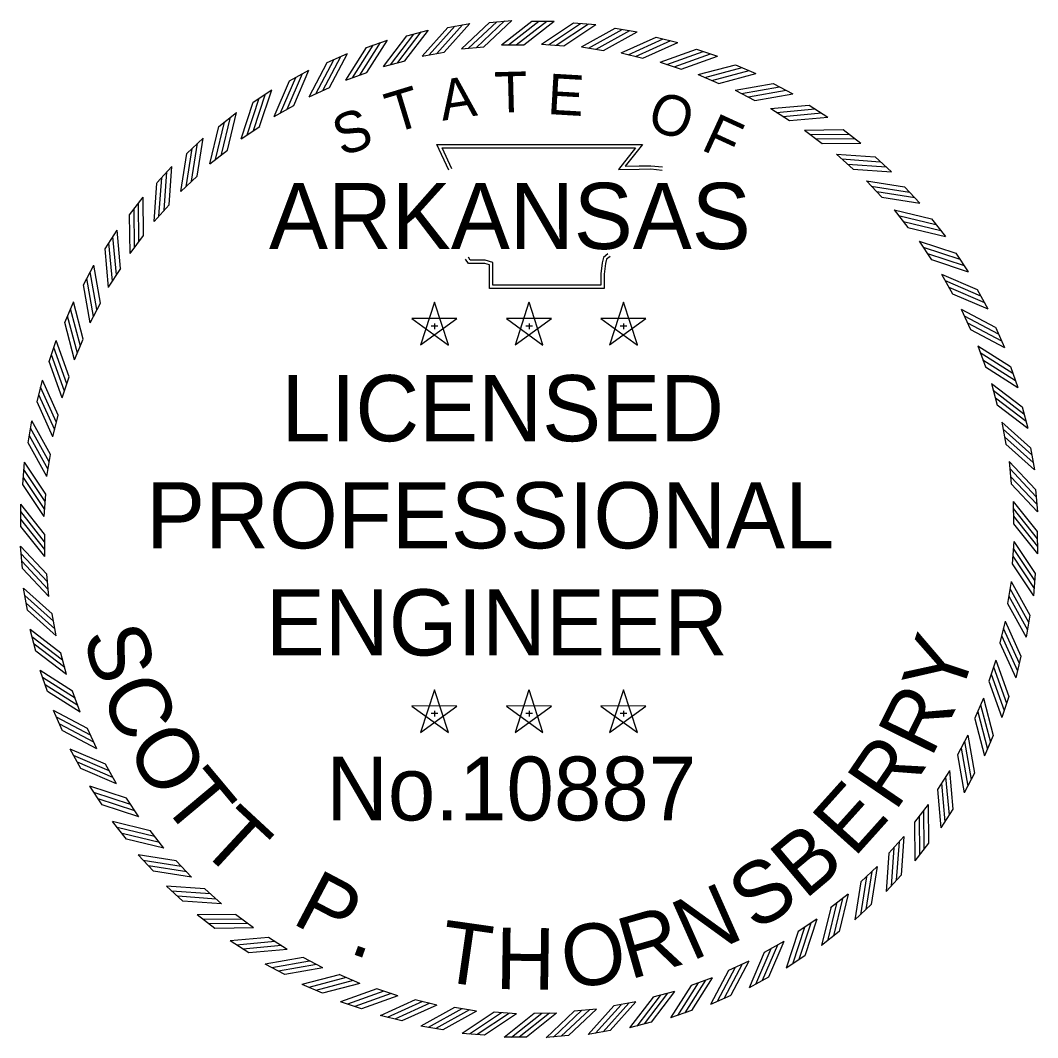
# Model space of a CAD drawing. Extents: x -4306 to 3843, y 131 to 8053.
# Drawn here: x 3046.5 to 3294.9, y 323.2 to 571.6 of the extents above; entities that cross this region are included whole.
import ezdxf

# ---------------------------------------------------------------- set-up
doc = ezdxf.new("R2010")
doc.units = 0
doc.layers.add('STAMP_PP', color=7, linetype='Continuous')

msp = doc.modelspace()

# ---------------------------------------------------------------- linework, layer by layer
at = {"layer": 'STAMP_PP'}
for p, q in [((3161.08, 571.13), (3166.5, 571.63)), ((3171.39, 571.43), (3176.83, 571.43)), ((3140.85, 567.86), (3146.11, 569.24)), ((3150.9, 569.91), (3156.26, 570.86)), ((3181.58, 571.02), (3187, 570.63)), ((3191.75, 569.7), (3197.12, 568.86)), ((3131.01, 564.98), (3136.14, 566.8)), ((3201.77, 567.55), (3207.06, 566.26)), ((3154.22, 564.68), (3159.65, 565.18)), ((3163.96, 565.64), (3169.41, 565.64)), ((3173.75, 565.8), (3179.19, 565.4)), ((3183.51, 565.14), (3188.9, 564.29)), ((3211.59, 564.57), (3216.75, 562.85)), ((3121.43, 561.3), (3126.4, 563.53)), ((3135.14, 560.37), (3140.42, 561.76)), ((3144.59, 562.92), (3149.96, 563.87)), ((3193.19, 563.68), (3198.49, 562.39)), ((3112.2, 556.85), (3116.96, 559.48)), ((3202.71, 561.42), (3207.89, 559.7)), ((3221.12, 560.8), (3226.13, 558.66)), ((3125.94, 557.05), (3131.08, 558.87)), ((3212.02, 558.39), (3217.03, 556.25)), ((3103.36, 551.64), (3107.89, 554.66)), ((3117.04, 552.98), (3122.01, 555.21)), ((3221.04, 554.6), (3225.86, 552.05)), ((3230.31, 556.24), (3235.12, 553.7)), ((3094.98, 545.72), (3099.24, 549.11)), ((3108.5, 548.19), (3113.27, 550.83)), ((3229.72, 550.08), (3234.32, 547.14)), ((3239.1, 550.95), (3243.68, 548.02)), ((3100.39, 542.71), (3104.93, 545.73)), ((3238, 544.85), (3242.33, 541.54)), ((3247.41, 544.95), (3251.74, 541.64)), ((3087.12, 539.14), (3091.09, 542.86)), ((3092.76, 536.57), (3097.04, 539.96)), ((3245.82, 538.96), (3249.86, 535.3)), ((3255.21, 538.28), (3259.24, 534.63)), ((3079.83, 531.92), (3083.48, 535.96)), ((3085.67, 529.83), (3089.64, 533.56)), ((3253.12, 532.45), (3256.85, 528.47)), ((3262.42, 530.99), (3266.14, 527.02)), ((3073.17, 524.13), (3076.47, 528.45)), ((3079.15, 522.53), (3082.81, 526.58)), ((3259.86, 525.35), (3263.25, 521.08)), ((3269.01, 523.13), (3272.39, 518.87)), ((3067.16, 515.81), (3070.1, 520.39)), ((3073.26, 514.71), (3076.57, 519.05)), ((3265.99, 517.72), (3269.02, 513.18)), ((3274.93, 514.75), (3277.94, 510.23)), ((3061.87, 507.03), (3064.41, 511.84)), ((3068.04, 506.44), (3070.98, 511.03)), ((3271.47, 509.61), (3274.11, 504.84)), ((3280.13, 505.92), (3282.76, 501.15)), ((3057.32, 497.84), (3059.46, 502.84)), ((3063.51, 497.76), (3066.06, 502.58)), ((3147.61, 502.79), (3144.21, 492.34)), ((3151, 492.35), (3147.62, 502.8)), ((3170.69, 502.79), (3167.28, 492.34)), ((3174.08, 492.35), (3170.7, 502.8)), ((3193.77, 502.79), (3190.36, 492.34)), ((3197.16, 492.35), (3193.77, 502.8)), ((3276.26, 501.08), (3278.5, 496.1)), ((3153.1, 498.8), (3142.11, 498.81)), ((3142.12, 498.8), (3151, 492.33)), ((3144.22, 492.35), (3153.11, 498.8)), ((3146.83, 497.04), (3148.46, 497.04)), ((3147.62, 497.63), (3147.62, 496.25)), ((3176.18, 498.8), (3165.19, 498.81)), ((3165.2, 498.8), (3174.08, 492.33)), ((3167.3, 492.35), (3176.19, 498.8)), ((3169.91, 497.04), (3171.54, 497.04)), ((3170.7, 497.63), (3170.7, 496.25)), ((3199.25, 498.8), (3188.27, 498.81)), ((3188.28, 498.8), (3197.16, 492.33)), ((3190.37, 492.35), (3199.27, 498.8)), ((3192.98, 497.04), (3194.62, 497.04)), ((3193.78, 497.63), (3193.78, 496.25)), ((3284.59, 496.68), (3286.82, 491.72)), ((3053.54, 488.3), (3055.26, 493.47)), ((3059.72, 488.74), (3061.86, 493.75)), ((3280.33, 492.18), (3282.15, 487.03)), ((3288.27, 487.11), (3290.08, 481.98)), ((3056.69, 479.43), (3058.41, 484.6)), ((3050.56, 478.49), (3051.85, 483.78)), ((3283.66, 482.97), (3285.04, 477.69)), ((3291.14, 477.26), (3292.53, 472)), ((3054.43, 469.91), (3055.72, 475.2)), ((3048.41, 468.46), (3049.25, 473.84)), ((3286.21, 473.52), (3287.15, 468.15)), ((3293.2, 467.21), (3294.14, 461.86)), ((3052.97, 460.23), (3053.82, 465.61)), ((3047.09, 458.29), (3047.49, 463.72)), ((3287.97, 463.89), (3288.47, 458.46)), ((3052.32, 450.46), (3052.72, 455.9)), ((3294.41, 457.03), (3294.91, 451.61)), ((3046.61, 448.05), (3046.56, 453.49)), ((3288.93, 454.15), (3288.98, 448.7)), ((3052.47, 440.68), (3052.42, 446.13)), ((3294.79, 446.78), (3294.84, 441.34)), ((3046.98, 437.8), (3046.48, 443.22)), ((3289.08, 444.37), (3288.68, 438.93)), ((3053.43, 430.94), (3052.93, 436.37)), ((3294.31, 436.54), (3293.91, 431.11)), ((3048.2, 427.61), (3047.25, 432.97)), ((3288.42, 434.6), (3287.58, 429.21)), ((3055.19, 421.31), (3054.24, 426.68)), ((3286.96, 424.92), (3285.67, 419.62)), ((3292.99, 426.36), (3292.14, 420.99)), ((3050.25, 417.57), (3048.87, 422.83)), ((3057.74, 411.86), (3056.35, 417.13)), ((3284.71, 415.4), (3282.99, 410.22)), ((3290.83, 416.34), (3289.55, 411.05)), ((3053.13, 407.72), (3051.32, 412.85)), ((3061.06, 402.65), (3059.24, 407.79)), ((3147.61, 408.16), (3144.21, 397.72)), ((3151, 397.72), (3147.62, 408.17)), ((3170.69, 408.16), (3167.28, 397.72)), ((3174.08, 397.72), (3170.7, 408.17)), ((3193.77, 408.16), (3190.36, 397.72)), ((3197.16, 397.72), (3193.77, 408.17)), ((3281.68, 406.09), (3279.53, 401.08)), ((3287.86, 406.52), (3286.14, 401.36)), ((3056.81, 398.15), (3054.58, 403.11)), ((3153.1, 404.17), (3142.11, 404.19)), ((3142.12, 404.17), (3151, 397.71)), ((3144.22, 397.72), (3153.11, 404.17)), ((3147.62, 403.01), (3147.62, 401.63)), ((3176.18, 404.17), (3165.19, 404.19)), ((3165.2, 404.17), (3174.08, 397.71)), ((3167.3, 397.72), (3176.19, 404.17)), ((3170.7, 403.01), (3170.7, 401.63)), ((3199.25, 404.17), (3188.27, 404.19)), ((3188.28, 404.17), (3197.16, 397.71)), ((3190.37, 397.72), (3199.27, 404.17)), ((3193.78, 403.01), (3193.78, 401.63)), ((3146.83, 402.42), (3148.46, 402.42)), ((3169.91, 402.42), (3171.54, 402.42)), ((3192.98, 402.42), (3194.62, 402.42)), ((3065.13, 393.75), (3062.9, 398.72)), ((3277.89, 397.07), (3275.33, 392.25)), ((3284.08, 396.99), (3281.94, 391.99)), ((3061.27, 388.91), (3058.63, 393.67)), ((3069.93, 385.22), (3067.29, 389.99)), ((3273.36, 388.39), (3270.42, 383.8)), ((3279.53, 387.8), (3276.98, 382.99)), ((3066.47, 380.07), (3063.45, 384.6)), ((3075.41, 377.11), (3072.38, 381.65)), ((3268.14, 380.11), (3264.83, 375.78)), ((3274.23, 379.01), (3271.3, 374.43)), ((3072.39, 371.7), (3069.01, 375.96)), ((3081.54, 369.48), (3078.15, 373.75)), ((3262.25, 372.3), (3258.59, 368.25)), ((3268.23, 370.7), (3264.93, 366.37)), ((3078.98, 363.84), (3075.25, 367.81)), ((3088.28, 362.38), (3084.55, 366.36)), ((3255.73, 364.99), (3251.75, 361.26)), ((3261.56, 362.91), (3257.92, 358.87)), ((3086.19, 356.55), (3082.15, 360.2)), ((3095.58, 355.87), (3091.54, 359.52)), ((3248.63, 358.25), (3244.36, 354.86)), ((3254.27, 355.69), (3250.31, 351.97)), ((3093.98, 349.88), (3089.66, 353.18)), ((3103.4, 349.98), (3099.06, 353.29)), ((3241, 352.12), (3236.47, 349.1)), ((3246.41, 349.1), (3242.15, 345.72)), ((3102.3, 343.88), (3097.72, 346.81)), ((3111.67, 344.75), (3107.08, 347.69)), ((3232.9, 346.64), (3228.12, 344)), ((3238.04, 343.19), (3233.51, 340.17)), ((3111.08, 338.58), (3106.27, 341.13)), ((3120.35, 340.23), (3115.53, 342.78)), ((3224.36, 341.85), (3219.39, 339.61)), ((3129.38, 336.44), (3124.36, 338.58)), ((3229.2, 337.98), (3224.44, 335.35)), ((3120.27, 334.03), (3115.27, 336.17)), ((3215.46, 337.78), (3210.32, 335.96)), ((3138.68, 333.4), (3133.51, 335.13)), ((3206.25, 334.46), (3200.98, 333.07)), ((3219.96, 333.52), (3215, 331.29)), ((3129.81, 330.26), (3124.65, 331.97)), ((3148.21, 331.15), (3142.91, 332.44)), ((3157.88, 329.69), (3152.5, 330.54)), ((3196.8, 331.91), (3191.43, 330.96)), ((3139.62, 327.28), (3134.34, 328.57)), ((3167.65, 329.03), (3162.21, 329.43)), ((3177.44, 329.18), (3171.98, 329.13)), ((3187.18, 330.14), (3181.75, 329.64)), ((3210.39, 329.84), (3205.26, 328.03)), ((3149.65, 325.12), (3144.28, 325.97)), ((3200.55, 326.97), (3195.28, 325.58)), ((3159.82, 323.8), (3154.39, 324.2)), ((3170.07, 323.33), (3164.62, 323.28)), ((3180.31, 323.7), (3174.9, 323.2)), ((3190.5, 324.91), (3185.14, 323.97))]:
    msp.add_line(p, q, dxfattribs=at)
for points in [[(3157.84, 565.04), (3164.7, 571.48)], [(3159.64, 565.19), (3166.5, 571.63)], [(3163.95, 565.64), (3171.38, 571.43)], [(3165.71, 565.62), (3173.13, 571.41)], [(3167.6, 565.66), (3175.02, 571.45)], [(3169.41, 565.65), (3176.83, 571.44)], [(3140.41, 561.76), (3146.12, 569.25)], [(3144.59, 562.92), (3150.89, 569.91)], [(3146.31, 563.2), (3152.62, 570.19)], [(3148.17, 563.57), (3154.47, 570.56)], [(3149.96, 563.87), (3156.26, 570.86)], [(3154.21, 564.68), (3161.08, 571.12)], [(3155.96, 564.82), (3162.82, 571.27)], [(3173.74, 565.79), (3181.57, 571.02)], [(3175.49, 565.65), (3183.31, 570.88)], [(3177.37, 565.55), (3185.2, 570.78)], [(3179.18, 565.4), (3187.01, 570.63)], [(3183.51, 565.14), (3191.74, 569.7)], [(3185.23, 564.85), (3193.47, 569.41)], [(3187.11, 564.59), (3195.34, 569.16)], [(3131.07, 558.87), (3136.14, 566.8)], [(3135.14, 560.36), (3140.84, 567.85)], [(3136.84, 560.79), (3142.54, 568.28)], [(3138.65, 561.32), (3144.36, 568.8)], [(3188.89, 564.3), (3197.13, 568.86)], [(3193.18, 563.68), (3201.77, 567.55)], [(3194.88, 563.25), (3203.46, 567.12)], [(3196.73, 562.84), (3205.31, 566.71)], [(3125.93, 557.04), (3131, 564.98)], [(3127.59, 557.61), (3132.66, 565.54)], [(3129.36, 558.28), (3134.42, 566.21)], [(3198.48, 562.39), (3207.07, 566.26)], [(3202.71, 561.42), (3211.58, 564.57)], [(3204.36, 560.85), (3213.24, 564)], [(3118.64, 553.67), (3123.03, 562)], [(3120.34, 554.49), (3124.74, 562.81)], [(3122, 555.22), (3126.4, 563.54)], [(3206.17, 560.3), (3215.04, 563.44)], [(3207.88, 559.71), (3216.76, 562.85)], [(3113.27, 550.83), (3116.96, 559.49)], [(3117.03, 552.97), (3121.43, 561.3)], [(3212.01, 558.39), (3221.11, 560.79)], [(3213.62, 557.69), (3222.72, 560.09)], [(3215.37, 556.98), (3224.47, 559.39)], [(3108.5, 548.18), (3112.19, 556.84)], [(3110.04, 549.01), (3113.73, 557.67)], [(3111.67, 549.96), (3115.37, 558.62)], [(3217.03, 556.25), (3226.13, 558.66)], [(3104.92, 545.73), (3107.89, 554.67)], [(3221.04, 554.6), (3230.31, 556.24)], [(3222.58, 553.77), (3231.85, 555.41)], [(3224.27, 552.92), (3233.54, 554.56)], [(3100.39, 542.7), (3103.36, 551.63)], [(3101.86, 543.66), (3104.82, 552.59)], [(3103.41, 544.74), (3106.37, 553.67)], [(3225.86, 552.06), (3235.13, 553.7)], [(3097.03, 539.96), (3099.25, 549.11)], [(3229.71, 550.08), (3239.09, 550.95)], [(3231.18, 549.12), (3240.55, 549.99)], [(3094.14, 537.64), (3096.36, 546.79)], [(3095.6, 538.85), (3097.82, 548)], [(3232.8, 548.13), (3242.17, 549.01)], [(3234.31, 547.14), (3243.69, 548.02)], [(3092.76, 536.57), (3094.98, 545.72)], [(3237.99, 544.85), (3247.4, 544.95)], [(3088.3, 532.34), (3089.76, 541.64)], [(3089.64, 533.56), (3091.09, 542.86)], [(3239.37, 543.78), (3248.79, 543.87)], [(3240.9, 542.66), (3250.31, 542.76)], [(3242.33, 541.55), (3251.74, 541.64)], [(3085.67, 529.83), (3087.12, 539.13)], [(3086.95, 531.01), (3088.41, 540.31)], [(3151.11, 535.02), (3148.21, 541.3), (3198.39, 541.33), (3194.2, 536.06), (3197.61, 536.11), (3200.46, 536.14), (3203.3, 535.83)], [(3151.84, 535.35), (3149.46, 540.5), (3196.74, 540.53), (3192.54, 535.24), (3197.62, 535.31), (3200.42, 535.35), (3203.22, 535.04)], [(3245.81, 538.96), (3255.2, 538.28)], [(3247.1, 537.78), (3256.49, 537.09)], [(3081.57, 525.24), (3082.25, 534.63)], [(3082.8, 526.57), (3083.48, 535.96)], [(3248.53, 536.54), (3257.92, 535.86)], [(3249.86, 535.31), (3259.25, 534.63)], [(3079.15, 522.52), (3079.83, 531.91)], [(3080.34, 523.81), (3081.02, 533.2)], [(3253.11, 532.45), (3262.41, 530.99)], [(3254.3, 531.16), (3263.6, 529.7)], [(3255.62, 529.81), (3264.92, 528.35)], [(3075.45, 517.62), (3075.35, 527.03)], [(3076.56, 519.05), (3076.47, 528.46)], [(3256.85, 528.47), (3266.15, 527.02)], [(3074.34, 516.09), (3074.24, 525.5)], [(3259.85, 525.35), (3269, 523.13)], [(3073.26, 514.71), (3073.16, 524.12)], [(3260.93, 523.97), (3270.08, 521.75)], [(3262.13, 522.51), (3271.28, 520.3)], [(3070.97, 511.03), (3070.1, 520.4)], [(3263.25, 521.08), (3272.4, 518.87)], [(3068.99, 507.9), (3068.12, 517.27)], [(3069.98, 509.51), (3069.1, 518.88)], [(3265.98, 517.72), (3274.92, 514.76)], [(3068.04, 506.43), (3067.16, 515.8)], [(3189.98, 514.61), (3188.93, 513.75), (3188.56, 512.4), (3188.27, 509.7), (3188.27, 506.98), (3161.85, 506.98), (3161.85, 510.87), (3161.85, 512.49), (3160.03, 513.05), (3156.36, 513.05), (3155.89, 513.77)], [(3266.94, 516.26), (3275.88, 513.29)], [(3268.02, 514.71), (3276.96, 511.74)], [(3066.06, 502.57), (3064.41, 511.84)], [(3190.49, 513.99), (3189.63, 513.29), (3189.35, 512.25), (3189.06, 509.65), (3189.06, 506.18), (3161.05, 506.18), (3161.05, 510.87), (3161.05, 511.91), (3159.91, 512.25), (3155.93, 512.25), (3155.22, 513.33)], [(3269.02, 513.19), (3277.95, 510.22)], [(3065.19, 500.98), (3063.55, 510.25)], [(3271.46, 509.61), (3280.12, 505.92)], [(3063.51, 497.75), (3061.87, 507.02)], [(3064.35, 499.29), (3062.7, 508.56)], [(3272.3, 508.07), (3280.96, 504.38)], [(3273.25, 506.44), (3281.91, 502.75)], [(3274.11, 504.85), (3282.77, 501.15)], [(3061.86, 493.75), (3059.46, 502.85)], [(3060.43, 490.33), (3058.02, 499.43)], [(3061.13, 492.09), (3058.73, 501.19)], [(3276.26, 501.08), (3284.58, 496.68)], [(3276.96, 499.48), (3285.28, 495.08)], [(3059.72, 488.73), (3057.32, 497.83)], [(3277.77, 497.77), (3286.1, 493.37)], [(3278.5, 496.11), (3286.83, 491.71)], [(3058.4, 484.6), (3055.26, 493.47)], [(3280.33, 492.18), (3288.26, 487.11)], [(3057.26, 481.08), (3054.11, 489.95)], [(3057.82, 482.88), (3054.67, 491.76)], [(3280.9, 490.52), (3288.83, 485.46)], [(3056.69, 479.42), (3053.54, 488.29)], [(3281.57, 488.76), (3289.5, 483.69)], [(3282.15, 487.04), (3290.09, 481.97)], [(3055.27, 473.44), (3051.4, 482.02)], [(3055.72, 475.2), (3051.85, 483.78)], [(3283.65, 482.97), (3291.14, 477.27)], [(3054.87, 471.6), (3051, 480.18)], [(3284.08, 481.28), (3291.57, 475.57)], [(3054.44, 469.9), (3050.57, 478.48)], [(3284.6, 479.46), (3292.09, 473.75)], [(3285.05, 477.7), (3292.53, 472)], [(3053.52, 463.82), (3048.95, 472.05)], [(3053.82, 465.61), (3049.25, 473.84)], [(3286.2, 473.53), (3293.19, 467.22)], [(3053.26, 461.95), (3048.7, 470.18)], [(3286.49, 471.8), (3293.48, 465.49)], [(3286.86, 469.94), (3293.85, 463.64)], [(3052.98, 460.22), (3048.41, 468.45)], [(3287.16, 468.16), (3294.15, 461.85)], [(3052.71, 455.89), (3047.48, 463.72)], [(3287.96, 463.9), (3294.41, 457.04)], [(3288.11, 462.15), (3294.55, 455.29)], [(3052.47, 452.2), (3047.24, 460.03)], [(3052.56, 454.09), (3047.33, 461.92)], [(3288.32, 460.27), (3294.77, 453.41)], [(3052.32, 450.46), (3047.09, 458.28)], [(3288.47, 458.47), (3294.92, 451.61)], [(3052.41, 446.12), (3046.56, 453.49)], [(3288.92, 454.16), (3294.78, 446.79)], [(3288.92, 452.41), (3294.78, 445.04)], [(3052.41, 444.31), (3046.56, 451.68)], [(3052.47, 442.42), (3046.62, 449.79)], [(3288.98, 450.52), (3294.84, 443.15)], [(3052.47, 440.67), (3046.62, 448.04)], [(3288.98, 448.7), (3294.84, 441.33)], [(3052.93, 436.36), (3046.48, 443.22)], [(3288.93, 442.63), (3294.16, 434.8)], [(3289.08, 444.37), (3294.31, 436.54)], [(3053.08, 434.55), (3046.63, 441.41)], [(3288.83, 440.74), (3294.06, 432.91)], [(3053.29, 432.67), (3046.84, 439.54)], [(3053.43, 430.93), (3046.99, 437.79)], [(3288.68, 438.93), (3293.91, 431.1)], [(3054.24, 426.67), (3047.25, 432.98)], [(3288.13, 432.88), (3292.7, 424.65)], [(3288.42, 434.61), (3292.99, 426.37)], [(3054.54, 424.88), (3047.55, 431.19)], [(3287.88, 431.01), (3292.44, 422.77)], [(3054.91, 423.03), (3047.92, 429.33)], [(3055.2, 421.3), (3048.21, 427.61)], [(3287.58, 429.22), (3292.15, 420.98)], [(3286.96, 424.93), (3290.83, 416.35)], [(3056.35, 417.13), (3048.86, 422.83)], [(3286.53, 423.23), (3290.4, 414.65)], [(3056.8, 415.37), (3049.31, 421.07)], [(3286.12, 421.39), (3289.99, 412.8)], [(3057.32, 413.55), (3049.83, 419.26)], [(3057.75, 411.85), (3050.26, 417.56)], [(3285.68, 419.63), (3289.55, 411.05)], [(3284.71, 415.41), (3287.85, 406.53)], [(3059.24, 407.79), (3051.31, 412.85)], [(3284.14, 413.75), (3287.29, 404.88)], [(3059.83, 406.07), (3051.9, 411.14)], [(3282.99, 410.23), (3286.14, 401.36)], [(3283.58, 411.94), (3286.73, 403.07)], [(3060.5, 404.3), (3052.57, 409.37)], [(3061.07, 402.65), (3053.14, 407.72)], [(3281.67, 406.1), (3284.08, 397)], [(3062.9, 398.72), (3054.57, 403.11)], [(3280.27, 402.74), (3282.67, 393.64)], [(3280.97, 404.5), (3283.37, 395.39)], [(3063.62, 397.06), (3055.3, 401.45)], [(3279.54, 401.08), (3281.94, 391.98)], [(3064.44, 395.35), (3056.11, 399.75)], [(3065.14, 393.75), (3056.82, 398.14)], [(3277.05, 395.54), (3278.69, 386.27)], [(3277.88, 397.08), (3279.53, 387.81)], [(3067.29, 389.98), (3058.63, 393.67)], [(3276.2, 393.85), (3277.85, 384.58)], [(3068.15, 388.39), (3059.49, 392.08)], [(3069.1, 386.75), (3060.44, 390.45)], [(3275.34, 392.25), (3276.98, 382.98)], [(3069.93, 385.21), (3061.27, 388.91)], [(3273.36, 388.4), (3274.23, 379.02)], [(3271.42, 385.32), (3272.29, 375.94)], [(3272.4, 386.93), (3273.28, 377.56)], [(3072.38, 381.64), (3063.45, 384.6)], [(3073.37, 380.12), (3064.44, 383.09)], [(3270.43, 383.8), (3271.3, 374.43)], [(3074.46, 378.57), (3065.52, 381.54)], [(3268.14, 380.12), (3268.23, 370.71)], [(3075.41, 377.1), (3066.48, 380.07)], [(3267.06, 378.74), (3267.16, 369.33)], [(3078.15, 373.74), (3069, 375.96)], [(3264.83, 375.78), (3264.93, 366.37)], [(3265.95, 377.21), (3266.04, 367.8)], [(3079.26, 372.31), (3070.11, 374.53)], [(3080.47, 370.86), (3071.32, 373.08)], [(3081.55, 369.48), (3072.4, 371.69)], [(3261.06, 371.02), (3260.38, 361.63)], [(3262.25, 372.3), (3261.57, 362.91)], [(3084.55, 366.35), (3075.25, 367.81)], [(3258.6, 368.25), (3257.92, 358.86)], [(3259.82, 369.59), (3259.14, 360.2)], [(3085.78, 365.02), (3076.48, 366.47)], [(3087.1, 363.67), (3077.8, 365.12)], [(3088.29, 362.38), (3078.98, 363.84)], [(3254.44, 363.81), (3252.99, 354.51)], [(3255.73, 365), (3254.28, 355.7)], [(3251.76, 361.26), (3250.3, 351.96)], [(3253.09, 362.49), (3251.64, 353.19)], [(3091.54, 359.52), (3082.15, 360.2)], [(3092.87, 358.29), (3083.48, 358.97)], [(3248.64, 358.26), (3246.42, 349.11)], [(3094.3, 357.05), (3084.91, 357.73)], [(3095.59, 355.87), (3086.2, 356.55)], [(3245.8, 355.98), (3243.58, 346.83)], [(3247.25, 357.18), (3245.04, 348.04)], [(3099.07, 353.28), (3089.65, 353.18)], [(3244.37, 354.86), (3242.15, 345.72)], [(3100.5, 352.16), (3091.08, 352.07)], [(3102.02, 351.05), (3092.61, 350.96)], [(3239.54, 351.17), (3236.58, 342.24)], [(3241.01, 352.13), (3238.04, 343.19)], [(3103.41, 349.98), (3093.99, 349.88)], [(3236.47, 349.1), (3233.51, 340.16)], [(3237.99, 350.09), (3235.03, 341.15)], [(3107.08, 347.68), (3097.71, 346.81)], [(3108.6, 346.69), (3099.23, 345.82)], [(3110.22, 345.71), (3100.84, 344.84)], [(3231.36, 345.81), (3227.66, 337.16)], [(3232.9, 346.65), (3229.2, 337.99)], [(3111.68, 344.75), (3102.31, 343.88)], [(3228.13, 344), (3224.44, 335.34)], [(3229.72, 344.86), (3226.03, 336.2)], [(3115.54, 342.77), (3106.27, 341.13)], [(3117.13, 341.91), (3107.86, 340.27)], [(3118.82, 341.06), (3109.55, 339.42)], [(3222.76, 341.15), (3218.37, 332.83)], [(3224.36, 341.86), (3219.97, 333.53)], [(3120.36, 340.23), (3111.09, 338.58)], [(3124.37, 338.57), (3115.26, 336.17)], [(3219.39, 339.61), (3215, 331.29)], [(3221.05, 340.34), (3216.66, 332.01)], [(3126.03, 337.85), (3116.92, 335.44)], [(3127.78, 337.14), (3118.68, 334.74)], [(3129.38, 336.44), (3120.28, 334.03)], [(3210.33, 335.96), (3205.26, 328.02)], [(3212.04, 336.55), (3206.97, 328.61)], [(3213.81, 337.22), (3208.74, 329.28)], [(3215.46, 337.78), (3210.4, 329.85)], [(3133.51, 335.12), (3124.64, 331.97)], [(3135.23, 334.53), (3126.35, 331.38)], [(3137.03, 333.97), (3128.16, 330.83)], [(3138.69, 333.41), (3129.82, 330.26)], [(3200.99, 333.07), (3195.28, 325.58)], [(3202.74, 333.51), (3197.04, 326.02)], [(3204.56, 334.03), (3198.85, 326.54)], [(3206.26, 334.46), (3200.55, 326.97)], [(3142.91, 332.43), (3134.33, 328.56)], [(3144.67, 331.99), (3136.09, 328.12)], [(3146.52, 331.58), (3137.93, 327.71)], [(3148.21, 331.15), (3139.63, 327.28)], [(3152.5, 330.53), (3144.27, 325.97)], [(3191.44, 330.96), (3185.14, 323.96)], [(3193.23, 331.25), (3186.92, 324.26)], [(3195.08, 331.62), (3188.78, 324.63)], [(3196.81, 331.91), (3190.5, 324.92)], [(3154.29, 330.23), (3146.06, 325.67)], [(3156.16, 329.98), (3147.93, 325.42)], [(3157.89, 329.69), (3149.66, 325.13)], [(3162.22, 329.43), (3154.39, 324.2)], [(3164.02, 329.28), (3156.2, 324.05)], [(3165.91, 329.18), (3158.08, 323.95)], [(3167.66, 329.04), (3159.83, 323.81)], [(3171.99, 329.13), (3164.62, 323.27)], [(3173.8, 329.13), (3166.43, 323.27)], [(3175.69, 329.19), (3168.32, 323.33)], [(3177.44, 329.19), (3170.07, 323.33)], [(3181.75, 329.64), (3174.89, 323.19)], [(3183.56, 329.79), (3176.7, 323.34)], [(3185.44, 330.01), (3178.58, 323.56)], [(3187.18, 330.15), (3180.32, 323.7)]]:
    msp.add_lwpolyline(points, dxfattribs=at)

# ---------------------------------------------------------------- texts
for s, height, rotation, p in [('T', 9.9, 1.4789, (3162.37, 549.07)), ('A', 9.9, 8.6788, (3149.58, 547.1)), ('E', 9.9, 356.672, (3175.03, 548.77)), ('T', 9.9, 16.9015, (3137.57, 543.96)), ('O', 9.9, 341.2218, (3199.07, 545.37)), ('S', 9.9, 19.7726, (3124.98, 538.31)), ('F', 9.9, 335.3628, (3212.41, 540.16)), ('S', 15.03, 286.9475, (3061.59, 421.47)), ('Y', 15.03, 71.7733, (3275.78, 405.43)), ('C', 15.03, 294.2435, (3065.77, 407.76)), ('R', 15.03, 63.7477, (3268.9, 391.25)), ('O', 15.03, 301.9044, (3071.99, 394.05)), ('R', 15.03, 55.7221, (3260.1, 378.16)), ('T', 15.03, 309.93, (3080.41, 380.72)), ('E', 15.03, 48.0613, (3250.08, 366.93)), ('T', 15.03, 317.226, (3089.62, 369.73)), ('B', 15.03, 40.0357, (3238.07, 356.71)), ('S', 15.03, 32.7397, (3226.01, 348.95)), ('P', 15.03, 332.1828, (3112.43, 351.3)), ('N', 15.03, 23.9845, (3210.39, 341.76)), ('R', 15.03, 15.9589, (3195.26, 337.33)), ('T', 15.03, 351.882, (3148.26, 337.1)), ('O', 15.03, 7.9332, (3179.65, 335.05)), ('H', 15.03, 359.178, (3162.46, 335.08)), ('.', 15.03, 340.2084, (3126.42, 344.03))]:
    msp.add_text(s, height=height, rotation=rotation, dxfattribs=at).set_placement(p)
for s, height, p in [('ARKANSAS', 16.155, (3107.2, 515.79)), ('LICENSED', 16.155, (3110.27, 468.84)), ('PROFESSIONAL', 16.1547, (3077.19, 442.69)), ('ENGINEER', 16.155, (3106.43, 416.53)), ('No.10887', 15.578, (3121.19, 376.25))]:
    msp.add_text(s, height=height, dxfattribs=at).set_placement(p)

doc.saveas('drawing.dxf')
